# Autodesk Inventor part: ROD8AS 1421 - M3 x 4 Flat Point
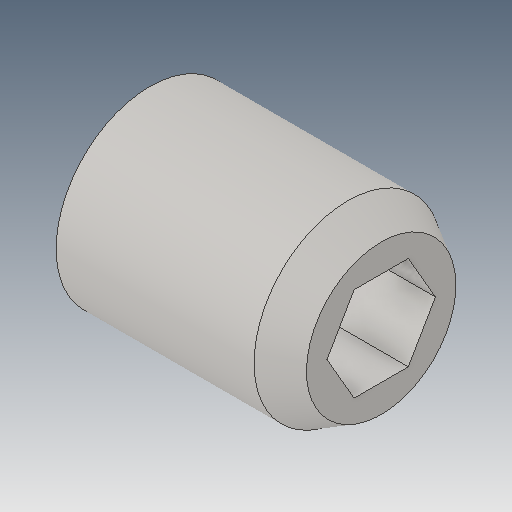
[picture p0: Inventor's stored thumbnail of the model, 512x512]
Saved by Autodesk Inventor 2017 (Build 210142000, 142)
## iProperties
Created: 2017-02
Part Number: ROD8AS 1421 - M3 x 4 Flat Point
Material: Generic
Document SubType Name: Modeling
Designer: JK
Density: 1 g/cm^3
Appearance: Default
Author: JK
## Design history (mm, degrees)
feature "Solid1"
body "Solid2"
